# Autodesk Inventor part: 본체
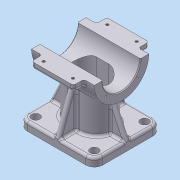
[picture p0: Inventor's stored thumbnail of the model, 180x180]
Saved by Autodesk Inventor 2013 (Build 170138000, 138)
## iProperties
Company: 한국ATC센터
Created: 2009-02
Part Number: 본체
Document SubType Name: Modeling
Designer: KYOUNG IL JANG
Density: 2.71 g/cm^3
Material: 알루미늄-6061
Vendor: CBT Solutions
Author: KYOUNG IL JANG
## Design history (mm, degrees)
sketch "스케치1"
  geometry: L1 (-45, 40)-(45, 40); L2 (45, 40)-(45, -40); L3 (45, -40)-(-45, -40); L4 (-45, -40)-(-45, 40); 3 further points
  constraints: 8 end point, 2 midpoint, 2 parallel, 1 horizontal, 1 horizontal alignment, 1 perpendicular, 1 vertical alignment
  dimensions: "d0" = 90 distance of L2.end L3.end; "d1" = 80 distance of L1.end L2.end
extrude "돌출1" new body sketch "스케치1" distance "d2" = 10; taper "d3" = 0 deg
sketch "스케치2"
  geometry: L1 (40, 0)-(-40, 0) reference; C1 r 32.5 at (0, 80); 2 further points
  constraints: 1 centre point, 1 midpoint, 1 vertical alignment
  dimensions: "d4" = 65 diameter of C1; "d5" = 80 distance from line of C1.centre L1
extrude "돌출2" join sketch "스케치2" stored distance "d6" = 75; taper "d7" = 0 deg
sketch "스케치3"
  geometry: L1 (-7.5, -20)-(7.5, -20); L2 (7.5, 20)-(-7.5, 20); A1 r 20 centre (7.5, 0) between (7.5, -20) and (7.5, 20); A2 r 20 centre (-7.5, 0) between (-7.5, 20) and (-7.5, -20); 2 further points
  constraints: 4 end point, 4 point on circle, 4 tangent, 2 centre point, 1 horizontal, 1 horizontal alignment, 1 midpoint, 1 parallel, 1 vertical alignment
  dimensions: "d8" = 20 radius of A2; "d9" = 55 dimension on A1 A2
extrude "돌출3" join sketch "스케치3" stored distance "d10" = 75; taper "d11" = 0 deg
fillet "모깎기1" dims "d12" = 10
sketch "스케치4"
  geometry: L1 (-45, 0)-(-45, 10) reference; L2 (37.5, 47.5)-(-37.5, 47.5) reference; L3 (-45, 10)-(-27.513, 47.5); 1 further point
  constraints: 2 end point, 1 point on line
  dimensions: "d13" = 25 deg angle of L3 L1
sketch "스케치5"
  geometry: L1 (-40, 0)-(-40, 10) reference; L2 (-40, 10)-(-22.912, 56.95); 2 further points
  constraints: 2 end point, 2 other
  dimensions: "d14" = 20 deg angle of L2 L1
feature "리브1" dims "d15" = 1, "d16" = 6, "d17" = 0
feature "리브2" dims "d18" = 1, "d19" = 6, "d20" = 0
fillet "모깎기2" dims "d21" = 3
fillet "모깎기3" dims "d22" = 3
fillet "모깎기4" dims "d23" = 3
fillet "모깎기5" dims "d24" = 3
fillet "모깎기6" dims "d25" = 3
fillet "모깎기7" dims "d26" = 3
fillet "모깎기8" dims "d27" = 3
sketch "스케치6"
  geometry: A1 r 10 centre (35, -30) between (35, -40) and (45, -30) reference; 1 further point
hole "구멍1" sketch "스케치6" at (35, -30) diameter "d28" = 10; stored, may be unused: countersink angle "d32" = 90 deg, drill point angle "d34" = 118 deg; dims "d29" = 6, "d30" = 4, "d31" = 2, "d33" = 8
hole "구멍2" diameter "d37" = 45; stored, may be unused: countersink angle "d41" = 90 deg, drill point angle "d43" = 118 deg; dims "d35" = 10, "d36" = 10, "d38" = 6, "d39" = 4, "d40" = 2, "d42" = 8
sketch "스케치7"
  geometry: C1 r 22.5 at (0, 0) reference; 2 further points
  dimensions: "d44" = 135 deg dimension on C1.centre point (-18.738, 18.738) point (80, 0); "d45" = 26.5 distance of point (-18.738, 18.738) C1.centre
hole "구멍3" sketch "스케치7" at (-18.738, 18.738) diameter "d46" = 2.459; stored, may be unused: countersink angle "d50" = 90 deg, drill point angle "d52" = 118 deg; dims "d47" = 8, "d48" = 4, "d49" = 2, "d51" = 10
node "작업 평면1"
sketch "스케치8"
  geometry: C1 r 10 at (0, 0); 1 further point
  constraints: 1 centre point, 1 coincident
  dimensions: "d57" = 20 diameter of C1
extrude "돌출4" join sketch "스케치8" stored distance "d58" = 75; taper "d59" = 0 deg
hole "구멍4" diameter "d62" = 8.376; stored, may be unused: countersink angle "d66" = 90 deg, drill point angle "d68" = 118 deg; dims "d60" = 10, "d61" = 10, "d63" = 7, "d64" = 4, "d65" = 2, "d67" = 10
chamfer "모따기1" distance "d69" = 1; stored, may be unused: second distance "d70" = 2, angle "d71" = 45 deg
fillet "모깎기9" dims "d72" = 3
sketch "스케치9"
  geometry: L1 (-31.623, 87.5)-(-45, 87.5); L2 (-45, 87.5)-(-45, 72.5); L3 (-45, 72.5)-(-31.623, 72.5); A1 r 32.5 centre (0, 80) between (-31.623, 87.5) and (-31.623, 72.5) reference; 1 further point
  constraints: 6 end point, 2 parallel, 2 point on circle, 1 horizontal, 1 perpendicular
  dimensions: "d73" = 15 distance of L1.end L2.end; "d74" = 45 distance from line of A1.centre L2
extrude "돌출5" join sketch "스케치9" stored distance "d75" = 50; taper "d76" = 0 deg
fillet "모깎기10" dims "d77" = 3
fillet "모깎기11" dims "d78" = 3
sketch "스케치10"
  geometry: L1 (-61.625, 62.366)-(0, 62.366); L2 (0, 62.366)-(0, -62.366); L3 (0, -62.366)-(-61.625, -62.366); L4 (-61.625, -62.366)-(-61.625, 62.366); C1 r 32.5 at (0, 0) reference; 2 further points
  constraints: 8 end point, 2 parallel, 1 coincident, 1 horizontal, 1 midpoint, 1 perpendicular
extrude "돌출6" cut sketch "스케치10" stored distance "d79" = 10; taper "d80" = 0 deg
node "작업 평면2"
sketch "스케치11"
  geometry: L1 (-7.5, -15)-(7.5, -15); L2 (7.5, 15)-(-7.5, 15); A1 r 20 centre (-7.5, 0) between (-7.5, 20) and (-26.807, 5.217) reference; A2 r 20 centre (7.5, 0) between (26.807, 5.217) and (7.5, 20) reference; A3 r 15 centre (7.5, 0) between (7.5, -15) and (7.5, 15); A4 r 15 centre (-7.5, 0) between (-7.5, 15) and (-7.5, -15); 1 further point
  constraints: 4 end point, 4 point on circle, 3 tangent, 2 centre point, 2 coincident, 1 horizontal, 1 parallel
  dimensions: "d82" = 15 radius of A4
extrude "돌출7" cut sketch "스케치11" stored distance "d83" = 10; taper "d84" = 0 deg
sketch "스케치12"
  geometry: 1 further point
hole "구멍5" sketch "스케치12" at (0, 0) diameter "d85" = 12; stored, may be unused: countersink angle "d89" = 90 deg, drill point angle "d91" = 118 deg; dims "d86" = 6, "d87" = 38, "d88" = 10, "d90" = 8
sketch "스케치13"
  geometry: L1 (-15.5, -12.5)-(-59.5, -12.5) reference; 3 further points
  constraints: 1 horizontal alignment
  dimensions: "d92" = 35 distance of point (-20, -5.5) point (-55, -5.5); "d93" = 17.5 horizontal distance of point (-37.5, 32.5) point (-55, -5.5) (= 0.5 x d92); "d94" = 7 distance from line of L1 point (-55, -5.5)
hole "구멍6" sketch "스케치13" at (-55, -5.5), (-20, -5.5) diameter "d95" = 3.242; stored, may be unused: countersink angle "d99" = 90 deg, drill point angle "d101" = 118 deg; dims "d96" = 6, "d97" = 38, "d98" = 10, "d100" = 8
sketch "스케치14"
  geometry: C1 r 10 at (0, 0); 1 further point
  constraints: 1 centre point, 1 coincident
  dimensions: "d102" = 20 diameter of C1
extrude "돌출8" cut sketch "스케치14" distance "d103" = 5; taper "d104" = 0 deg
node "솔리드1"
mirror "대칭1"
mirror "대칭2"
mirror "대칭3"
mirror "대칭4"
pattern_circular "원형 패턴1" dims angle "d54" = 360 deg
mirror "대칭5"
mirror "대칭6"
mirror "대칭7"
other parameters: "d56" = -117
